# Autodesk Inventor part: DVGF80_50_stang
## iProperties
Created: 2010-04
Part Number: DVGF80_50_stang
Document SubType Name: Modeling
Designer: TB
Mass: 656.555 g
Surface Area: 573.106 cm^2
Volume: 656.555 cm^3
Density: 1 g/cm^3
Author: TB
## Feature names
1. Revolution1
2. Fillet1
3. Revolution2
4. Extrusion1
5. Extrusion2
6. Fillet2
7. Chamfer2
8. Chamfer3
